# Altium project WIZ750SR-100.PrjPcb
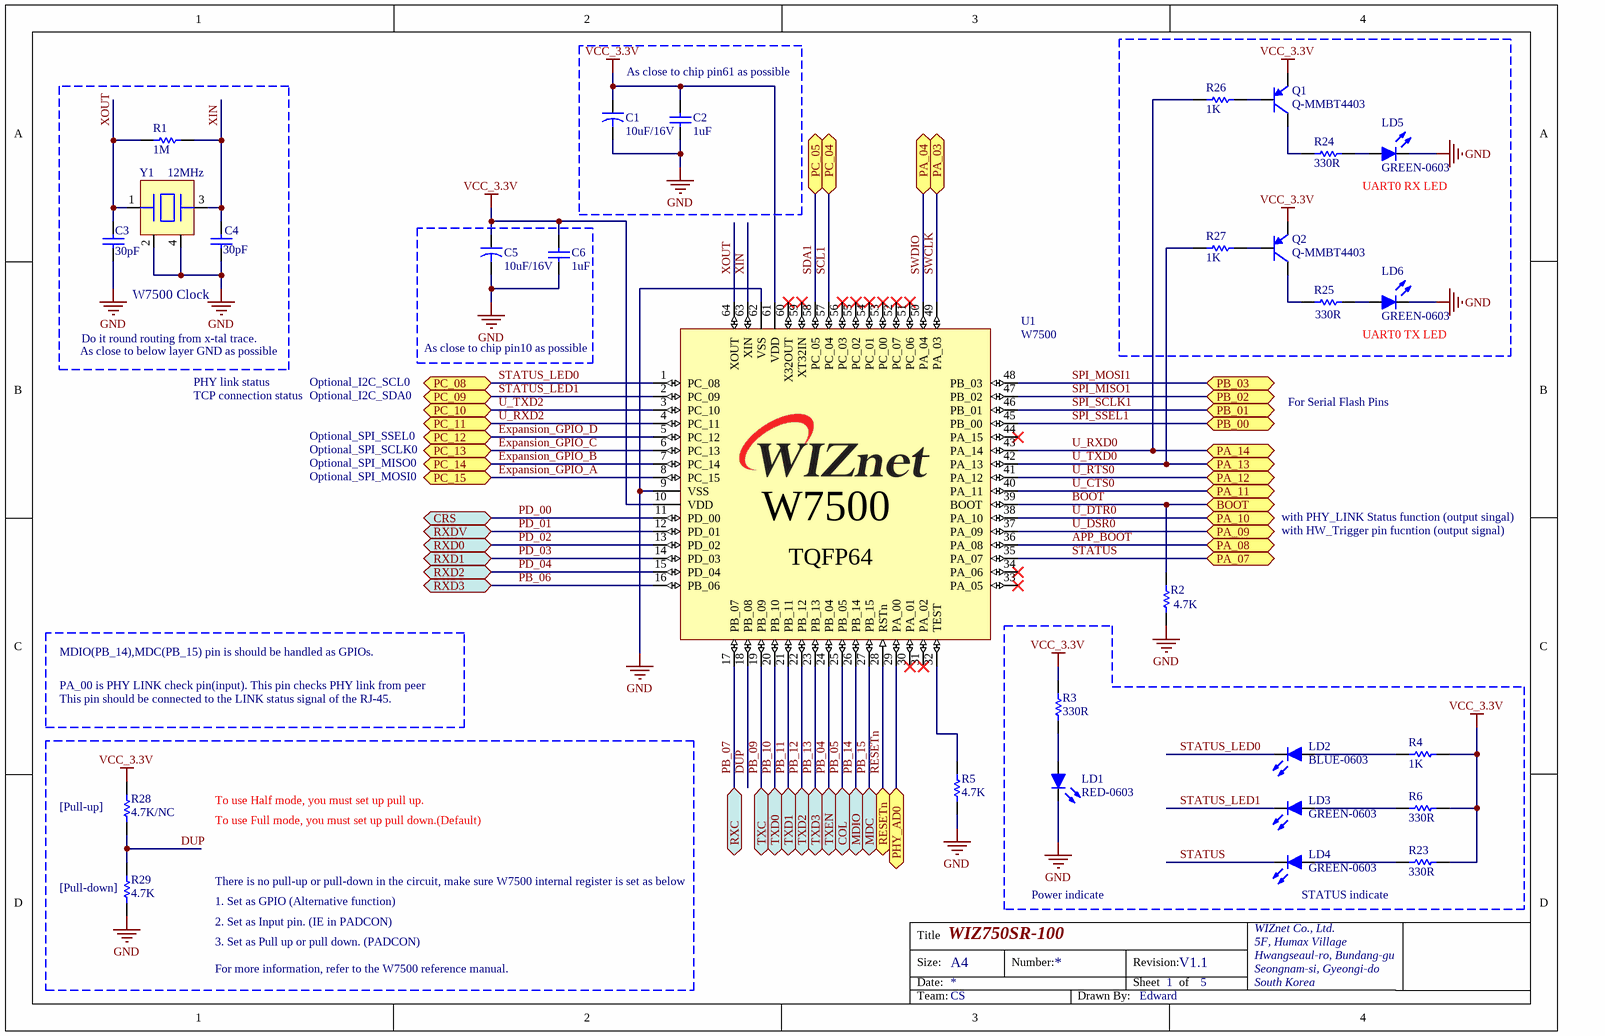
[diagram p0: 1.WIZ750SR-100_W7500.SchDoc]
5 sheets, 76 parts. Net scope: flat (ports and power ports of the same name join across sheets).
Board file: WIZ750SR-100_V1.1.PcbDoc
Sheets:
  1.WIZ750SR-100_W7500.SchDoc
  2.WIZ750SR-100_IP101GRI.SchDoc
  3.WIZ750SR-100_OPTIONAL.SchDoc
  4.WIZ750SR-100_PINOUT.SchDoc
  5.WIZ750SR-100_ETC.SchDoc

## Sheet 1.WIZ750SR-100_W7500.SchDoc: WIZ750SR-100
size A4; DrawnBy: Edward; Revision: V1.1; SheetNumber: 1; SheetTotal: 5; Team: CS

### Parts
C1  10uF/16V  [CAP-A Size]
C2  1uF  [CAP-0402]
C3  30pF  [CAP-0402]
C4  30pF  [CAP-0402]
C5  10uF/16V  [CAP-A Size]
C6  1uF  [CAP-0402]
LD1  RED-0603  [LED-0603-RED]
LD2  BLUE-0603  [LED-0603-BLUE]
LD3  GREEN-0603  [LED-0603-GREEN]
LD4  GREEN-0603  [LED-0603-GREEN]
LD5  GREEN-0603  [LED-0603-GREEN]
LD6  GREEN-0603  [LED-0603-GREEN]
Q1  Q-MMBT4403  [Q-MMBT4403-SOT23]
Q2  Q-MMBT4403  [Q-MMBT4403-SOT23]
R1  1M  [RES-0402]
R2  4.7K  [RES-0402]
R3  330R  [RES-0402]
R4  1K  [RES-0402]
R5  4.7K  [RES-0402]
R6  330R  [RES-0402]
R23  330R  [RES-0402]
R24  330R  [RES-0402]
R25  330R  [RES-0402]
R26  1K  [RES-0402]
R27  1K  [RES-0402]
R28  4.7K/NC  [RES-0402]
R29  4.7K  [RES-0402]
U1  W7500  [W7500-LQFP64]
Y1  12MHz  [OSC-TZ1067B]

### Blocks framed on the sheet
W7500 Clock: C3 C4 R1 Y1
As close to chip pin61 as possible: C1 C2
As close to chip pin10 as possible: C5 C6

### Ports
BOOT, COL, CRS, MDC, MDIO, PA_03, PA_04, PA_07, PA_08, PA_09, PA_10, PA_11, PA_12, PA_13, PA_14, PB_00, PB_01, PB_02, PB_03, PC_04, PC_05, PC_08, PC_09, PC_10, PC_11, PC_12, PC_13, PC_14, PC_15, PHY_AD0, RESETn, RXC, RXD0, RXD1, RXD2, RXD3, RXDV, TXC, TXD0, TXD1, TXD2, TXD3, TXEN

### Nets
GND: C1.2 C2.1 C3.1 C4.1 C5.2 C6.1 LD1.2(K) LD5.2(K) LD6.2(K) R2.2 R5.1 R29.1 U1.9(VSS) U1.62(VSS) Y1.2 Y1.4
VCC_3.3V: C1.1 C2.2 C5.1 C6.2 Q1.2(E) Q2.2(E) R3.1 R4.2 R6.2 R23.2 R28.2 U1.10(VDD) U1.61(VDD)
APP_BOOT: U1.36(PA_08) ; port PA_08
BOOT: R2.1 U1.39(BOOT) ; port BOOT
DUP: R28.1 R29.2 U1.18(PB_08)
Expansion_GPIO_A: U1.8(PC_15) ; port PC_15
Expansion_GPIO_B: U1.7(PC_14) ; port PC_14
Expansion_GPIO_C: U1.6(PC_13) ; port PC_13
Expansion_GPIO_D: U1.5(PC_12) ; port PC_12
PB_04: U1.24(PB_04) ; port TXEN
PB_05: U1.25(PB_05) ; port COL
PB_06: U1.16(PB_06) ; port RXD3
PB_07: U1.17(PB_07) ; port RXC
PB_09: U1.19(PB_09) ; port TXC
PB_10: U1.20(PB_10) ; port TXD0
PB_11: U1.21(PB_11) ; port TXD1
PB_12: U1.22(PB_12) ; port TXD2
PB_13: U1.23(PB_13) ; port TXD3
PB_14: U1.26(PB_14) ; port MDIO
PB_15: U1.27(PB_15) ; port MDC
PD_00: U1.11(PD_00) ; port CRS
PD_01: U1.12(PD_01) ; port RXDV
PD_02: U1.13(PD_02) ; port RXD0
PD_03: U1.14(PD_03) ; port RXD1
PD_04: U1.15(PD_04) ; port RXD2
PHY_AD0: U1.29(PA_00) ; port PHY_AD0
RESETn: U1.28(RSTn) ; port RESETn
SCL1: U1.57(PC_04) ; port PC_04
SDA1: U1.58(PC_05) ; port PC_05
SPI_MISO1: U1.47(PB_02) ; port PB_02
SPI_MOSI1: U1.48(PB_03) ; port PB_03
SPI_SCLK1: U1.46(PB_01) ; port PB_01
SPI_SSEL1: U1.45(PB_00) ; port PB_00
STATUS: LD4.2(K) U1.35(PA_07) ; port PA_07
STATUS_LED0: LD2.2(K) U1.1(PC_08) ; port PC_08
STATUS_LED1: LD3.2(K) U1.2(PC_09) ; port PC_09
SWCLK: U1.49(PA_03) ; port PA_03
SWDIO: U1.50(PA_04) ; port PA_04
U_CTS0: U1.40(PA_11) ; port PA_11
U_DSR0: U1.37(PA_09) ; port PA_09
U_DTR0: U1.38(PA_10) ; port PA_10
U_RTS0: U1.41(PA_12) ; port PA_12
U_RXD0: R26.2 U1.43(PA_14) ; port PA_14
U_RXD2: U1.4(PC_11) ; port PC_11
U_TXD0: R27.2 U1.42(PA_13) ; port PA_13
U_TXD2: U1.3(PC_10) ; port PC_10
XIN: C4.2 R1.2 U1.63(XIN) Y1.3
XOUT: C3.2 R1.1 U1.64(XOUT) Y1.1
NetLD1_1: LD1.1(A) R3.2
NetLD2_1: LD2.1(A) R4.1
NetLD3_1: LD3.1(A) R6.1
NetLD4_1: LD4.1(A) R23.1
NetLD5_1: LD5.1(A) R24.1
NetLD6_1: LD6.1(A) R25.2
NetQ1_1: Q1.1(B) R26.1
NetQ1_3: Q1.3(C) R24.2
NetQ2_1: Q2.1(B) R27.1
NetQ2_3: Q2.3(C) R25.1
NetR5_2: R5.2 U1.32(TEST)

Not connected (* = marked no-connect by the designer): U1 30(PA_01)* 31(PA_02)* 33(PA_05)* 34(PA_06)* 44(PA_15)* 51(PC_06)* 52(PC_07)* 53(PC_00)* 54(PC_01)* 55(PC_02)* 56(PC_03)* 59(XT32IN)* 60(X32OUT)*

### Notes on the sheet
- UART0 RX LED
- As close to below layer GND as possible
- Do it round routing from x-tal trace.
- PHY link status
- Optional_I2C_SCL0
- UART0 TX LED
- TCP connection status
- Optional_I2C_SDA0
- Optional_SPI_SSEL0
- For Serial Flash Pins
- Optional_SPI_SCLK0
- Optional_SPI_MISO0
- Optional_SPI_MOSI0
- with PHY_LINK Status function (output singal)
- with HW_Trigger pin fucntion (output signal)
- MDIO(PB_14),MDC(PB_15) pin is should be handled as GPIOs.
- PA_00 is PHY LINK check pin(input). This pin checks PHY link from peer
- This pin should be connected to the LINK status signal of the RJ-45.
- (near R28) [Pull-up]
- To use Half mode, you must set up pull up.
- To use Full mode, you must set up pull down.(Default)
- (near R29) [Pull-down]
- There is no pull-up or pull-down in the circuit, make sure W7500 internal register is set as below
- 1. Set as GPIO (Alternative function)
- 2. Set as Input pin. (IE in PADCON)
- Power indicate
- STATUS indicate
- 3. Set as Pull up or pull down. (PADCON)
- For more information, refer to the W7500 reference manual.

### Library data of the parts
C1 C5 = CAP-A Size: Tantla CAP A Size EIA/IECQ 3216
C2-C4 C6 = CAP-0402: Ceramic CAP 0402(1005)
LD1-LD6 = LED-0603
Q1 Q2 = Q-MMBT4403: PNP General-Purpose Amplifier
R1-R6 R23-R29 = RES-0402
U1 = W7500: WIZnet ARM Cortex-M0
Y1 = OSC-TZ1067B-12MHz: X-tal 12MHz,3.2x2.5 SMD, CL=20pF

## Sheet 2.WIZ750SR-100_IP101GRI.SchDoc: WIZ750SR-100
size A4; DrawnBy: Edward; Revision: V1.1; SheetNumber: 2; SheetTotal: 5; Team: CS
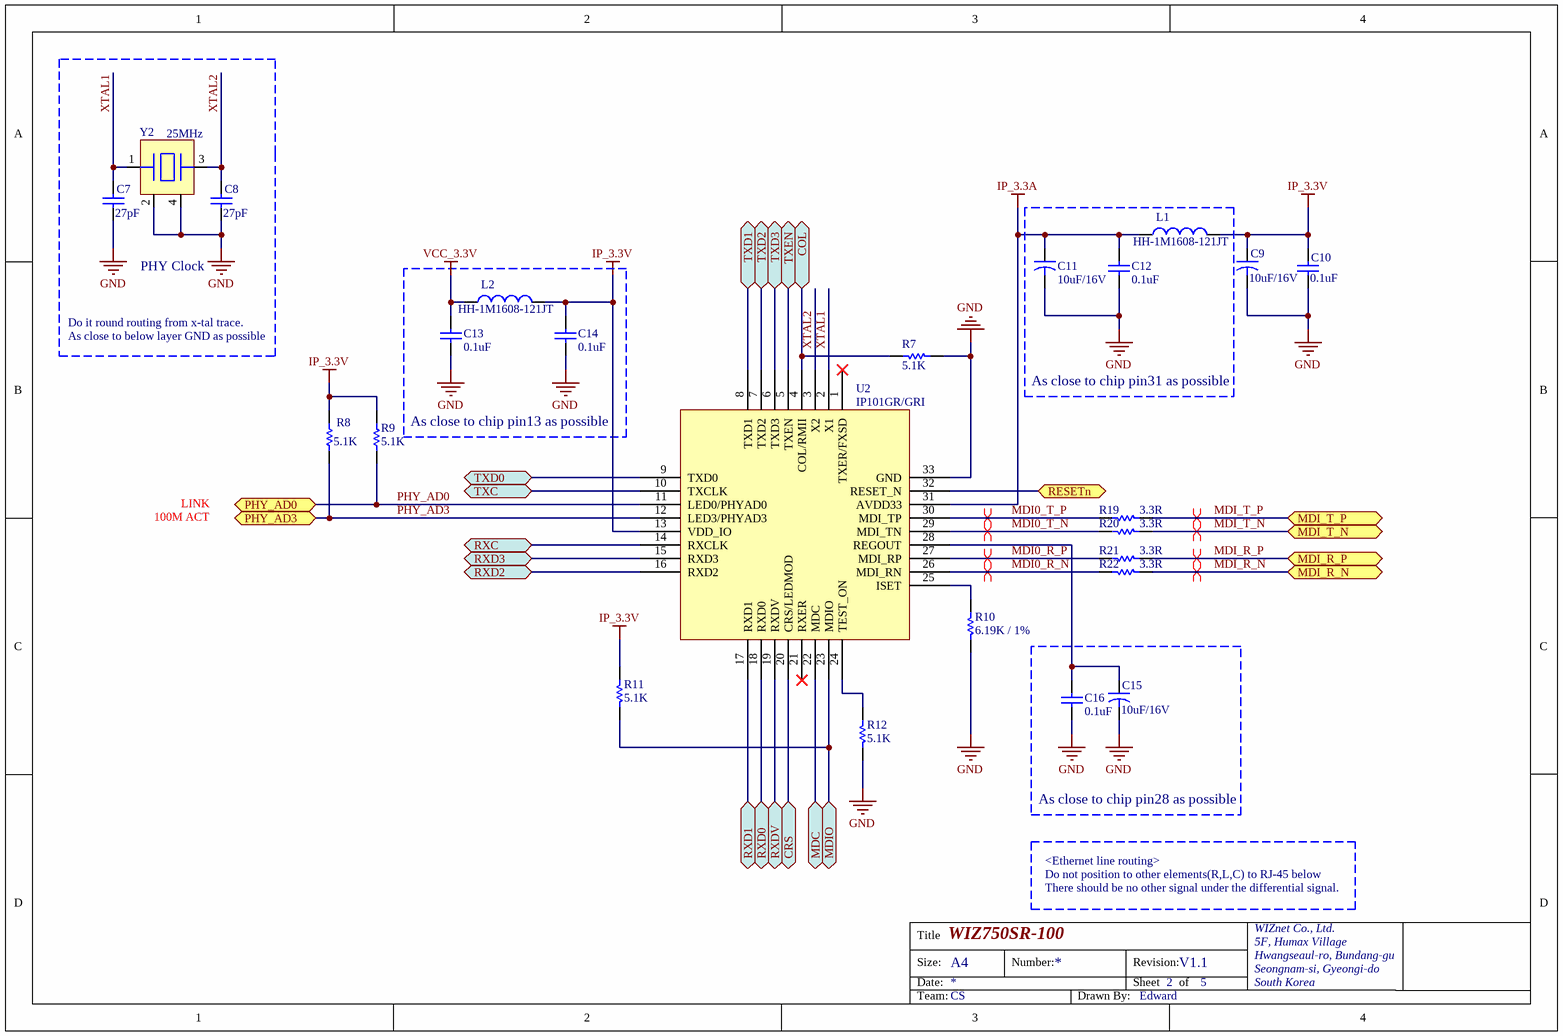
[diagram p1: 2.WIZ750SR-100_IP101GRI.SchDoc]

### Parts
C7  27pF  [CAP-0402]
C8  27pF  [CAP-0402]
C9  10uF/16V  [CAP-A Size]
C10  0.1uF  [CAP-0402]
C11  10uF/16V  [CAP-A Size]
C12  0.1uF  [CAP-0402]
C13  0.1uF  [CAP-0402]
C14  0.1uF  [CAP-0402]
C15  10uF/16V  [CAP-A Size]
C16  0.1uF  [CAP-0402]
L1  HH-1M1608-121JT  [IND-0603]
L2  HH-1M1608-121JT  [IND-0603]
R7  5.1K  [RES-0402]
R8  5.1K  [RES-0402]
R9  5.1K  [RES-0402]
R10  6.19K / 1%  [RES-0402]
R11  5.1K  [RES-0402]
R12  5.1K  [RES-0402]
R19  3.3R  [RES-0402]
R20  3.3R  [RES-0402]
R21  3.3R  [RES-0402]
R22  3.3R  [RES-0402]
U2  IP101GR/GRI  [QFN32(0.4/4X4)]
Y2  25MHz  [OSC-82J0626]

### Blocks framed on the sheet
PHY Clock: C7 C8 Y2
As close to chip pin31 as possible: C11 C12 L1
As close to chip pin13 as possible: C13 C14 L2
As close to chip pin28 as possible: C15 C16

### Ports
COL, CRS, MDC, MDI_R_N, MDI_R_P, MDI_T_N, MDI_T_P, MDIO, PHY_AD0, PHY_AD3, RESETn, RXC, RXD0, RXD1, RXD2, RXD3, RXDV, TXC, TXD0, TXD1, TXD2, TXD3, TXEN

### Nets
GND: C7.1 C8.1 C9.2 C10.1 C11.2 C12.1 C13.1 C14.2 C15.2 C16.1 R7.1 R10.1 R12.1 U2.33(GND) Y2.2 Y2.4
IP_3.3A: C11.1 C12.2 L1.1 U2.31(AVDD33)
IP_3.3V: C9.1 C10.2 C14.1 L1.2 L2.2 R8.1 R9.1 R11.2 U2.13(VDD_IO)
VCC_3.3V: C13.2 L2.1
MDI0_R_N: R22.2 U2.26(MDI_RN)
MDI0_R_P: R21.2 U2.27(MDI_RP)
MDI0_T_N: R20.2 U2.29(MDI_TN)
MDI0_T_P: R19.2 U2.30(MDI_TP)
MDI_R_N: R22.1 ; port MDI_R_N
MDI_R_P: R21.1 ; port MDI_R_P
MDI_T_N: R20.1 ; port MDI_T_N
MDI_T_P: R19.1 ; port MDI_T_P
PB_04: U2.5(TXEN) ; port TXEN
PB_05: R7.2 U2.4(COL/RMII) ; port COL
PB_06: U2.15(RXD3) ; port RXD3
PB_07: U2.14(RXCLK) ; port RXC
PB_09: U2.10(TXCLK) ; port TXC
PB_10: U2.9(TXD0) ; port TXD0
PB_11: U2.8(TXD1) ; port TXD1
PB_12: U2.7(TXD2) ; port TXD2
PB_13: U2.6(TXD3) ; port TXD3
PB_14: R11.1 U2.23(MDIO) ; port MDIO
PB_15: U2.22(MDC) ; port MDC
PD_00: U2.20(CRS/LEDMOD) ; port CRS
PD_01: U2.19(RXDV) ; port RXDV
PD_02: U2.18(RXD0) ; port RXD0
PD_03: U2.17(RXD1) ; port RXD1
PD_04: U2.16(RXD2) ; port RXD2
PHY_AD0: R9.2 U2.11(LED0/PHYAD0) ; port PHY_AD0
PHY_AD3: R8.2 U2.12(LED3/PHYAD3) ; port PHY_AD3
RESETn: U2.32(RESET_N) ; port RESETn
XTAL1: C7.2 U2.2(X1) Y2.1
XTAL2: C8.2 U2.3(X2) Y2.3
NetC15_1: C15.1 C16.2 U2.28(REGOUT)
NetR10_2: R10.2 U2.25(ISET)
NetR12_2: R12.2 U2.24(TEST_ON)

Not connected (* = marked no-connect by the designer): U2 1(TXER/FXSD)* 21(RXER)*

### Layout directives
differential pair: MDI0_R_N, MDI0_R_P, MDI0_T_N, MDI0_T_P, MDI_R_N, MDI_R_P, MDI_T_N, MDI_T_P

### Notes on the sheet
- Do it round routing from x-tal trace.
- As close to below layer GND as possible
- 100M ACT
- LINK
- <Ethernet line routing>
- Do not position to other elements(R,L,C) to RJ-45 below
- There should be no other signal under the differential signal.

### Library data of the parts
C7 C8 C10 C12-C14 C16 = CAP-0402: Ceramic CAP 0402(1005)
C9 C11 C15 = CAP-A Size: Tantla CAP A Size EIA/IECQ 3216
L1 L2 = IND-0603: Inductor 0603(1608)
R7 R10-R12 R19-R22 = RES-0402
R8 R9 = RES-0603: RES-0402
U2 = IP101GR/GRI: Pakage: VQFN-32
Y2 = OSC-82J0626-25MHz: X-tal 25MHz,3.2x2.5 SMD, CL=18pF

## Sheet 3.WIZ750SR-100_OPTIONAL.SchDoc: WIZ750SR-100
size A4; DrawnBy: Edward; Revision: V1.1; SheetNumber: 3; SheetTotal: 5; Team: CS
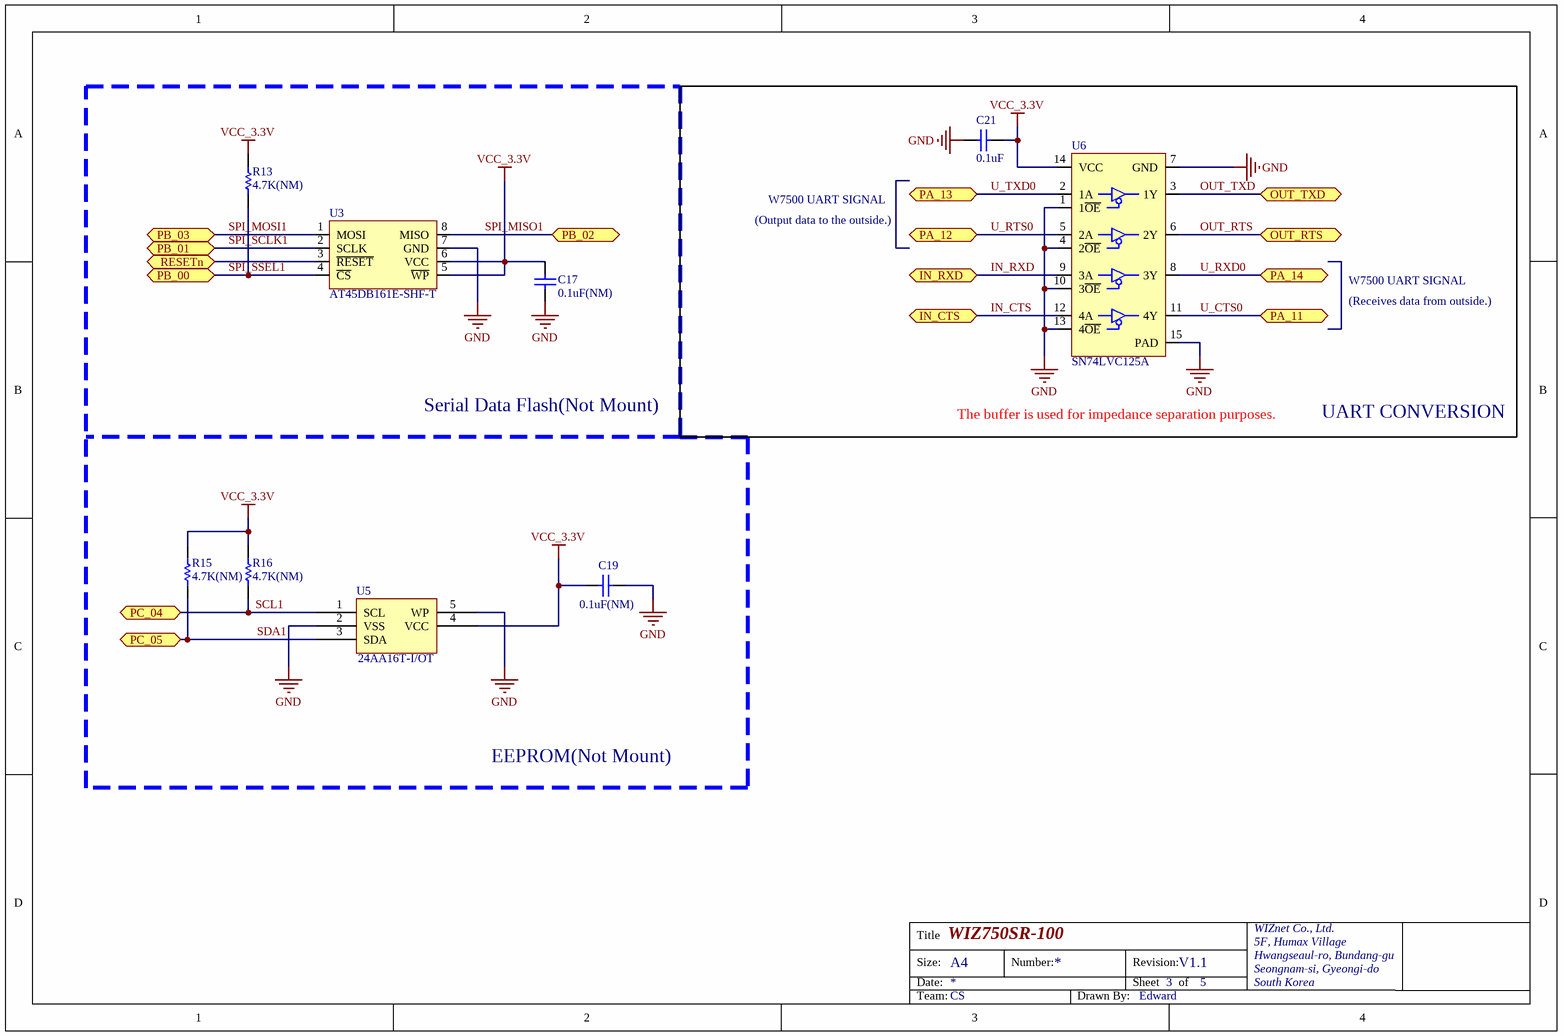
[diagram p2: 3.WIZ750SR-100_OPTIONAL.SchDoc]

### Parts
C17  0.1uF(NM)  [CAP-0402]
C19  0.1uF(NM)  [CAP-0402]
C21  0.1uF  [CAP-0402]
R13  4.7K(NM)  [RES-0402]
R15  4.7K(NM)  [RES-0402]
R16  4.7K(NM)  [RES-0402]
U3  AT45DB161E-SHF-T  [SO-08-EIAJ]
U5  24AA16T-I/OT  [SOT-23-5L]
U6  SN74LVC125A  [SN74LVC125A]

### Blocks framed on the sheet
UART CONVERSION: C21 U6

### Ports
IN_CTS, IN_RXD, OUT_RTS, OUT_TXD, PA_11, PA_12, PA_13, PA_14, PB_00, PB_01, PB_02, PB_03, PC_04, PC_05, RESETn

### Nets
GND: C17.2 C19.1 C21.2 U3.7(GND) U5.2(VSS) U5.5(WP) U6.1(1~{OE}) U6.4(2~{OE}) U6.7(GND) U6.10(3~{OE}) U6.13(4~{OE}) U6.15(PAD)
VCC_3.3V: C17.1 C19.2 C21.1 R13.2 R15.2 R16.2 U3.5(~{WP}) U3.6(VCC) U5.4(VCC) U6.14(VCC)
IN_CTS: U6.12(4A) ; port IN_CTS
IN_RXD: U6.9(3A) ; port IN_RXD
OUT_RTS: U6.6(2Y) ; port OUT_RTS
OUT_TXD: U6.3(1Y) ; port OUT_TXD
RESETn: U3.3(~{RESET}) ; port RESETn
SCL1: R16.1 U5.1(SCL) ; port PC_04
SDA1: R15.1 U5.3(SDA) ; port PC_05
SPI_MISO1: U3.8(MISO) ; port PB_02
SPI_MOSI1: U3.1(MOSI) ; port PB_03
SPI_SCLK1: U3.2(SCLK) ; port PB_01
SPI_SSEL1: R13.1 U3.4(~{CS}) ; port PB_00
U_CTS0: U6.11(4Y) ; port PA_11
U_RTS0: U6.5(2A) ; port PA_12
U_RXD0: U6.8(3Y) ; port PA_14
U_TXD0: U6.2(1A) ; port PA_13

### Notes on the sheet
- (Output data to the outside.)
- W7500 UART SIGNAL
- (Receives data from outside.)
- Serial Data Flash(Not Mount)
- The buffer is used for impedance separation purposes.
- EEPROM(Not Mount)

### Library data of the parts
C17 C19 C21 = CAP-0402: Ceramic CAP 0402(1005)
R13 R15 R16 = RES-0402
U3 = AT45DB161E-SHF-T: 16-Mbit DataFlash, 2.3V or 2.5V Minimum SPI Serial Flash Memory
U5 = 24AAxxT-i-OT: SOT-23
U6 = SN74LVC125A: Quadruple Bus Buffer Gate With 3-State Outputs

## Sheet 4.WIZ750SR-100_PINOUT.SchDoc: WIZ750SR-100
size A4; DrawnBy: Edward; Revision: V1.1; SheetNumber: 4; SheetTotal: 5; Team: CS
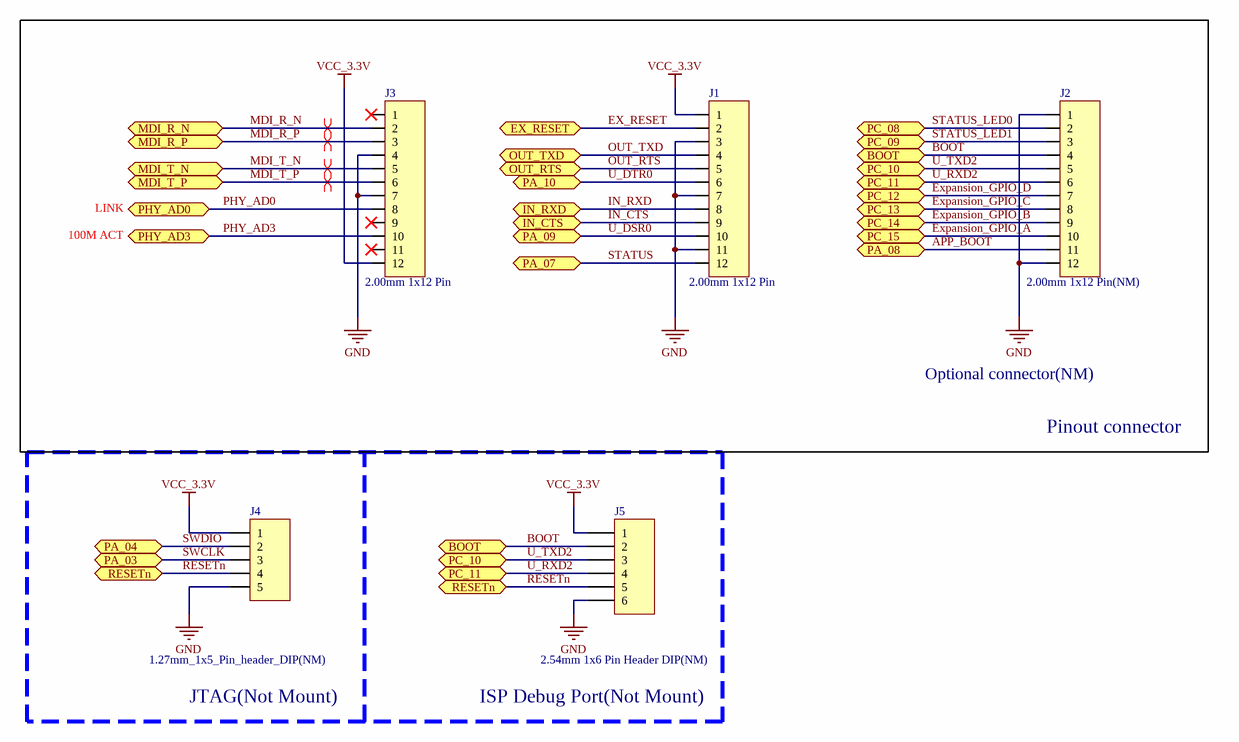
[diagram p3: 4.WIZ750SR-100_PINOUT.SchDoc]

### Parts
J1  2.00mm 1x12 Pin  [IDC-1X12(2MM)]
J2  2.00mm 1x12 Pin(NM)  [IDC-1X12(2MM)]
J3  2.00mm 1x12 Pin  [IDC-1X12(2MM)]
J4  1.27mm_1x5_Pin_header_DIP(NM)  [IDC-1X5(1.27MM)]
J5  2.54mm 1x6 Pin Header DIP(NM)  [IDC-1X6]

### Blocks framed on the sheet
Pinout connector: J1-J3

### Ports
BOOT, EX_RESET, IN_CTS, IN_RXD, MDI_R_N, MDI_R_P, MDI_T_N, MDI_T_P, OUT_RTS, OUT_TXD, PA_03, PA_04, PA_07, PA_08, PA_09, PA_10, PC_08, PC_09, PC_10, PC_11, PC_12, PC_13, PC_14, PC_15, PHY_AD0, PHY_AD3, RESETn

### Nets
GND: J1.3 J1.7 J1.11 J2.1 J2.12 J3.4 J3.7 J4.5 J5.6
VCC_3.3V: J1.1 J3.12 J4.1 J5.1
APP_BOOT: J2.11 ; port PA_08
BOOT: J2.4 J5.2 ; port BOOT
EX_RESET: J1.2 ; port EX_RESET
Expansion_GPIO_A: J2.10 ; port PC_15
Expansion_GPIO_B: J2.9 ; port PC_14
Expansion_GPIO_C: J2.8 ; port PC_13
Expansion_GPIO_D: J2.7 ; port PC_12
IN_CTS: J1.9 ; port IN_CTS
IN_RXD: J1.8 ; port IN_RXD
MDI_R_N: J3.2 ; port MDI_R_N
MDI_R_P: J3.3 ; port MDI_R_P
MDI_T_N: J3.5 ; port MDI_T_N
MDI_T_P: J3.6 ; port MDI_T_P
OUT_RTS: J1.5 ; port OUT_RTS
OUT_TXD: J1.4 ; port OUT_TXD
PHY_AD0: J3.8 ; port PHY_AD0
PHY_AD3: J3.10 ; port PHY_AD3
RESETn: J4.4 J5.5 ; port RESETn
STATUS: J1.12 ; port PA_07
STATUS_LED0: J2.2 ; port PC_08
STATUS_LED1: J2.3 ; port PC_09
SWCLK: J4.3 ; port PA_03
SWDIO: J4.2 ; port PA_04
U_DSR0: J1.10 ; port PA_09
U_DTR0: J1.6 ; port PA_10
U_RXD2: J2.6 J5.4 ; port PC_11
U_TXD2: J2.5 J5.3 ; port PC_10

Not connected (* = marked no-connect by the designer): J3 1* 9* 11*

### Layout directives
differential pair: MDI_R_N, MDI_R_P, MDI_T_N, MDI_T_P

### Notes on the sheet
- 100M ACT
- LINK
- Optional connector(NM)
- JTAG(Not Mount)
- ISP Debug Port(Not Mount)

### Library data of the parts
J1-J3 = Header 1x12 (2.00mm): pin header 2.00mm 1x12
J4 = 1.27mm_1x5_Pin_header_DIP
J5 = Header 6: Header, 6-Pin

## Sheet 5.WIZ750SR-100_ETC.SchDoc: WIZ750SR-100
size A4; DrawnBy: Edward; Revision: V1.1; SheetNumber: 5; SheetTotal: 5; Team: CS
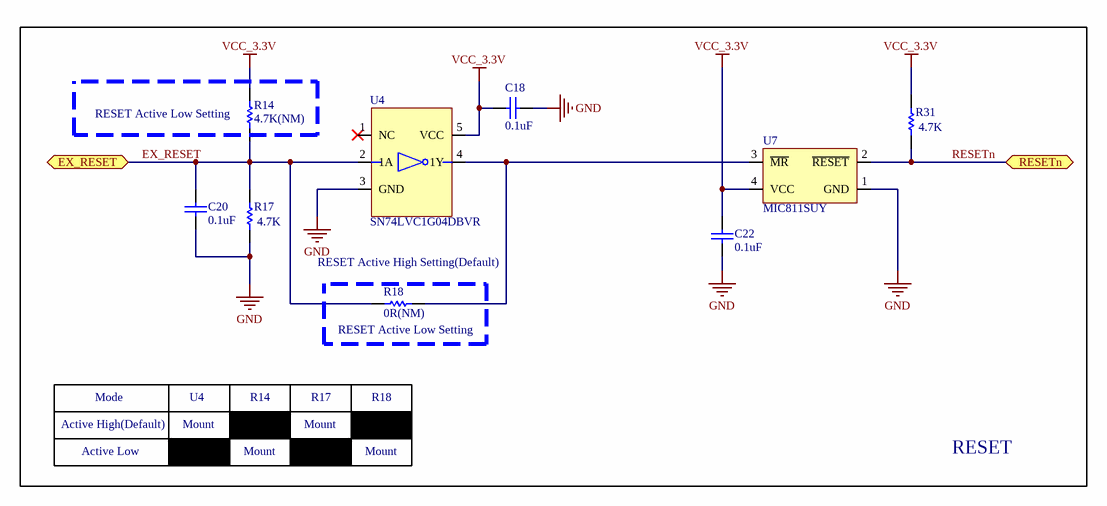
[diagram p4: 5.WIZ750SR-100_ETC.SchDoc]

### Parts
C18  0.1uF  [CAP-0402]
C20  0.1uF  [CAP-0402]
C22  0.1uF  [CAP-0402]
R14  4.7K(NM)  [RES-0402]
R17  4.7K  [RES-0402]
R18  0R(NM)  [RES-0402]
R31  4.7K  [RES-0402]
U4  SN74LVC1G04DBVR  [SOT-23-5L]
U7  MIC811SUY  [MIC811SUY/SOT-143]

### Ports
EX_RESET, RESETn

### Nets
GND: C18.1 C20.1 C22.2 R17.1 U4.3(GND) U7.1(GND)
VCC_3.3V: C18.2 C22.1 R14.2 R31.2 U4.5(VCC) U7.4(VCC)
EX_RESET: C20.2 R14.1 R17.2 R18.2 U4.2(1A) ; port EX_RESET
RESETn: R31.1 U7.2(~{RESET}) ; port RESETn
NetR18_1: R18.1 U4.4(1Y) U7.3(~{MR})

Not connected (* = marked no-connect by the designer): U4 1(NC)*

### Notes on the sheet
- (near R14) RESET Active Low Setting
- (near R18) RESET Active High Setting(Default)
- (near R18) RESET Active Low Setting
- Active High(Default)
- Mode
- Mount
- U4
- R14
- R17
- R18
- Active Low
- RESET

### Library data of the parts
C18 C20 C22 = CAP-0402: Ceramic CAP 0402(1005)
R14 R17 R18 R31 = RES-0402
U4 = SN74LVC1G04DBVR: IC, INVERTER, SINGLE, SMD, SOT-23-5
U7 = MIC811SUY: Microprocessor Reset Circuits

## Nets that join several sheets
GND: 1.WIZ750SR-100_W7500 (16 pins), 2.WIZ750SR-100_IP101GRI (16 pins), 3.WIZ750SR-100_OPTIONAL (12 pins), 4.WIZ750SR-100_PINOUT (9 pins), 5.WIZ750SR-100_ETC (6 pins)
VCC_3.3V: 1.WIZ750SR-100_W7500 (13 pins), 2.WIZ750SR-100_IP101GRI (C13.2 L2.1), 3.WIZ750SR-100_OPTIONAL (10 pins), 4.WIZ750SR-100_PINOUT (J1.1 J3.12 J4.1 J5.1), 5.WIZ750SR-100_ETC (6 pins)
APP_BOOT: 1.WIZ750SR-100_W7500 (U1.36), 4.WIZ750SR-100_PINOUT (J2.11)
BOOT: 1.WIZ750SR-100_W7500 (R2.1 U1.39), 4.WIZ750SR-100_PINOUT (J2.4 J5.2)
EX_RESET: 4.WIZ750SR-100_PINOUT (J1.2), 5.WIZ750SR-100_ETC (5 pins)
Expansion_GPIO_A: 1.WIZ750SR-100_W7500 (U1.8), 4.WIZ750SR-100_PINOUT (J2.10)
Expansion_GPIO_B: 1.WIZ750SR-100_W7500 (U1.7), 4.WIZ750SR-100_PINOUT (J2.9)
Expansion_GPIO_C: 1.WIZ750SR-100_W7500 (U1.6), 4.WIZ750SR-100_PINOUT (J2.8)
Expansion_GPIO_D: 1.WIZ750SR-100_W7500 (U1.5), 4.WIZ750SR-100_PINOUT (J2.7)
IN_CTS: 3.WIZ750SR-100_OPTIONAL (U6.12), 4.WIZ750SR-100_PINOUT (J1.9)
IN_RXD: 3.WIZ750SR-100_OPTIONAL (U6.9), 4.WIZ750SR-100_PINOUT (J1.8)
MDI_R_N: 2.WIZ750SR-100_IP101GRI (R22.1), 4.WIZ750SR-100_PINOUT (J3.2)
MDI_R_P: 2.WIZ750SR-100_IP101GRI (R21.1), 4.WIZ750SR-100_PINOUT (J3.3)
MDI_T_N: 2.WIZ750SR-100_IP101GRI (R20.1), 4.WIZ750SR-100_PINOUT (J3.5)
MDI_T_P: 2.WIZ750SR-100_IP101GRI (R19.1), 4.WIZ750SR-100_PINOUT (J3.6)
OUT_RTS: 3.WIZ750SR-100_OPTIONAL (U6.6), 4.WIZ750SR-100_PINOUT (J1.5)
OUT_TXD: 3.WIZ750SR-100_OPTIONAL (U6.3), 4.WIZ750SR-100_PINOUT (J1.4)
PB_04: 1.WIZ750SR-100_W7500 (U1.24), 2.WIZ750SR-100_IP101GRI (U2.5)
PB_05: 1.WIZ750SR-100_W7500 (U1.25), 2.WIZ750SR-100_IP101GRI (R7.2 U2.4)
PB_06: 1.WIZ750SR-100_W7500 (U1.16), 2.WIZ750SR-100_IP101GRI (U2.15)
PB_07: 1.WIZ750SR-100_W7500 (U1.17), 2.WIZ750SR-100_IP101GRI (U2.14)
PB_09: 1.WIZ750SR-100_W7500 (U1.19), 2.WIZ750SR-100_IP101GRI (U2.10)
PB_10: 1.WIZ750SR-100_W7500 (U1.20), 2.WIZ750SR-100_IP101GRI (U2.9)
PB_11: 1.WIZ750SR-100_W7500 (U1.21), 2.WIZ750SR-100_IP101GRI (U2.8)
PB_12: 1.WIZ750SR-100_W7500 (U1.22), 2.WIZ750SR-100_IP101GRI (U2.7)
PB_13: 1.WIZ750SR-100_W7500 (U1.23), 2.WIZ750SR-100_IP101GRI (U2.6)
PB_14: 1.WIZ750SR-100_W7500 (U1.26), 2.WIZ750SR-100_IP101GRI (R11.1 U2.23)
PB_15: 1.WIZ750SR-100_W7500 (U1.27), 2.WIZ750SR-100_IP101GRI (U2.22)
PD_00: 1.WIZ750SR-100_W7500 (U1.11), 2.WIZ750SR-100_IP101GRI (U2.20)
PD_01: 1.WIZ750SR-100_W7500 (U1.12), 2.WIZ750SR-100_IP101GRI (U2.19)
PD_02: 1.WIZ750SR-100_W7500 (U1.13), 2.WIZ750SR-100_IP101GRI (U2.18)
PD_03: 1.WIZ750SR-100_W7500 (U1.14), 2.WIZ750SR-100_IP101GRI (U2.17)
PD_04: 1.WIZ750SR-100_W7500 (U1.15), 2.WIZ750SR-100_IP101GRI (U2.16)
PHY_AD0: 1.WIZ750SR-100_W7500 (U1.29), 2.WIZ750SR-100_IP101GRI (R9.2 U2.11), 4.WIZ750SR-100_PINOUT (J3.8)
PHY_AD3: 2.WIZ750SR-100_IP101GRI (R8.2 U2.12), 4.WIZ750SR-100_PINOUT (J3.10)
RESETn: 1.WIZ750SR-100_W7500 (U1.28), 2.WIZ750SR-100_IP101GRI (U2.32), 3.WIZ750SR-100_OPTIONAL (U3.3), 4.WIZ750SR-100_PINOUT (J4.4 J5.5), 5.WIZ750SR-100_ETC (R31.1 U7.2)
SCL1: 1.WIZ750SR-100_W7500 (U1.57), 3.WIZ750SR-100_OPTIONAL (R16.1 U5.1)
SDA1: 1.WIZ750SR-100_W7500 (U1.58), 3.WIZ750SR-100_OPTIONAL (R15.1 U5.3)
SPI_MISO1: 1.WIZ750SR-100_W7500 (U1.47), 3.WIZ750SR-100_OPTIONAL (U3.8)
SPI_MOSI1: 1.WIZ750SR-100_W7500 (U1.48), 3.WIZ750SR-100_OPTIONAL (U3.1)
SPI_SCLK1: 1.WIZ750SR-100_W7500 (U1.46), 3.WIZ750SR-100_OPTIONAL (U3.2)
SPI_SSEL1: 1.WIZ750SR-100_W7500 (U1.45), 3.WIZ750SR-100_OPTIONAL (R13.1 U3.4)
STATUS: 1.WIZ750SR-100_W7500 (LD4.2 U1.35), 4.WIZ750SR-100_PINOUT (J1.12)
STATUS_LED0: 1.WIZ750SR-100_W7500 (LD2.2 U1.1), 4.WIZ750SR-100_PINOUT (J2.2)
STATUS_LED1: 1.WIZ750SR-100_W7500 (LD3.2 U1.2), 4.WIZ750SR-100_PINOUT (J2.3)
SWCLK: 1.WIZ750SR-100_W7500 (U1.49), 4.WIZ750SR-100_PINOUT (J4.3)
SWDIO: 1.WIZ750SR-100_W7500 (U1.50), 4.WIZ750SR-100_PINOUT (J4.2)
U_CTS0: 1.WIZ750SR-100_W7500 (U1.40), 3.WIZ750SR-100_OPTIONAL (U6.11)
U_DSR0: 1.WIZ750SR-100_W7500 (U1.37), 4.WIZ750SR-100_PINOUT (J1.10)
U_DTR0: 1.WIZ750SR-100_W7500 (U1.38), 4.WIZ750SR-100_PINOUT (J1.6)
U_RTS0: 1.WIZ750SR-100_W7500 (U1.41), 3.WIZ750SR-100_OPTIONAL (U6.5)
U_RXD0: 1.WIZ750SR-100_W7500 (R26.2 U1.43), 3.WIZ750SR-100_OPTIONAL (U6.8)
U_RXD2: 1.WIZ750SR-100_W7500 (U1.4), 4.WIZ750SR-100_PINOUT (J2.6 J5.4)
U_TXD0: 1.WIZ750SR-100_W7500 (R27.2 U1.42), 3.WIZ750SR-100_OPTIONAL (U6.2)
U_TXD2: 1.WIZ750SR-100_W7500 (U1.3), 4.WIZ750SR-100_PINOUT (J2.5 J5.3)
